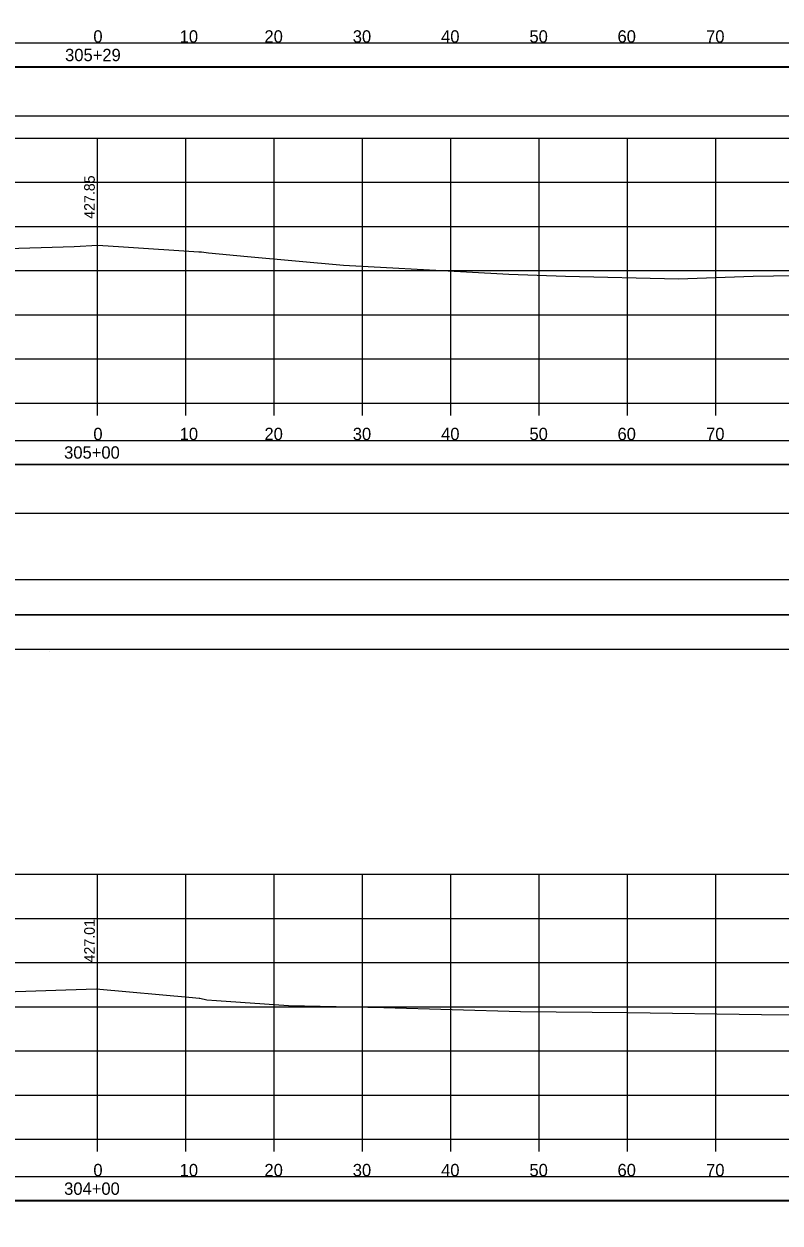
# Model space of a CAD drawing. Extents: x 1371057 to 1372761, y 380005 to 390517.
# Drawn here: x 1372589.5 to 1372675.1, y 389663.8 to 389799.6 of the extents above; entities that cross this region are included whole.
import ezdxf

# ---------------------------------------------------------------- set-up
doc = ezdxf.new("R2010")
doc.units = 0
for name, color, linetype in [('R_Axis', 7, 'Continuous'), ('R_Axis Annot', 7, 'Continuous'), ('R_Border', 7, 'Continuous'), ('R_Dimension', 7, 'Continuous'), ('R_Exist Surface', 7, 'Continuous'), ('R_Grid', 7, 'Continuous'), ('R_No Plot', 7, 'Continuous'), ('R_Xsect Elev', 7, 'Continuous')]:
    doc.layers.add(name, color=color, linetype=linetype)

msp = doc.modelspace()

# ---------------------------------------------------------------- linework, layer by layer
at = {"layer": 'R_Axis'}
for p, q in [((1372447.84, 389756.66), (1372747.84, 389756.66)), ((1372597.84, 389755.26), (1372597.84, 389756.66)), ((1372607.84, 389755.26), (1372607.84, 389756.66)), ((1372617.84, 389755.26), (1372617.84, 389756.66)), ((1372627.84, 389755.26), (1372627.84, 389756.66)), ((1372637.84, 389755.26), (1372637.84, 389756.66)), ((1372647.84, 389755.26), (1372647.84, 389756.66)), ((1372657.84, 389755.26), (1372657.84, 389756.66)), ((1372667.84, 389755.26), (1372667.84, 389756.66)), ((1372447.84, 389673.32), (1372747.84, 389673.32)), ((1372597.84, 389671.92), (1372597.84, 389673.32)), ((1372607.84, 389671.92), (1372607.84, 389673.32)), ((1372617.84, 389671.92), (1372617.84, 389673.32)), ((1372627.84, 389671.92), (1372627.84, 389673.32)), ((1372637.84, 389671.92), (1372637.84, 389673.32)), ((1372647.84, 389671.92), (1372647.84, 389673.32)), ((1372657.84, 389671.92), (1372657.84, 389673.32)), ((1372667.84, 389671.92), (1372667.84, 389673.32))]:
    msp.add_line(p, q, dxfattribs=at)
at = {"layer": 'R_Border'}
for p, q in [((1372756.02, 389736.66), (1372439.84, 389736.66)), ((1372439.84, 389728.78), (1372756.02, 389728.78)), ((1372592.36, 389728.52), (1372592.36, 389728.52)), ((1372592.36, 389728.52), (1372592.36, 389728.52))]:
    msp.add_line(p, q, dxfattribs=at)
at = {"layer": 'R_Dimension'}
for points in [[(1372445.42, 389794.69), (1372750.16, 389794.69), (1372750.16, 389797.39), (1372445.42, 389797.39)], [(1372445.47, 389789.19), (1372750.2, 389789.19), (1372750.2, 389794.71), (1372445.47, 389794.71)], [(1372445.42, 389749.69), (1372750.16, 389749.69), (1372750.16, 389752.39), (1372445.42, 389752.39)], [(1372445.47, 389744.19), (1372750.2, 389744.19), (1372750.2, 389749.71), (1372445.47, 389749.71)], [(1372445.42, 389666.35), (1372750.16, 389666.35), (1372750.16, 389669.05), (1372445.42, 389669.05)], [(1372445.47, 389660.85), (1372750.2, 389660.85), (1372750.2, 389666.37), (1372445.47, 389666.37)]]:
    msp.add_lwpolyline(points, close=True, dxfattribs=at)
at = {"layer": 'R_Exist Surface'}
for points in [[(1372586.4, 389774.1), (1372595.19, 389774.39), (1372597.87, 389774.52), (1372600.79, 389774.33), (1372609.31, 389773.79), (1372609.64, 389773.76), (1372610.4, 389773.68), (1372614.84, 389773.24), (1372625.68, 389772.26), (1372639.64, 389771.5), (1372644.42, 389771.25), (1372650.83, 389771.03), (1372663.61, 389770.72), (1372672.07, 389771.01), (1372683.56, 389771.21), (1372691.95, 389770.91), (1372705.91, 389770.55), (1372715.2, 389770.59), (1372727.99, 389770.76), (1372733.23, 389770.79), (1372738.81, 389770.7), (1372744.62, 389770.6), (1372747.84, 389770.57)], [(1372586.27, 389689.98), (1372597.71, 389690.34), (1372608.59, 389689.35), (1372609.36, 389689.28), (1372609.42, 389689.27), (1372610.24, 389689.11), (1372611.32, 389689.02), (1372619.49, 389688.44), (1372630.28, 389688.21), (1372645.74, 389687.79), (1372657.9, 389687.65), (1372673.02, 389687.45), (1372684.15, 389687.38), (1372695.61, 389687.31), (1372717.55, 389687.46), (1372717.69, 389687.46), (1372735.12, 389687.87), (1372736.13, 389687.89), (1372747.84, 389687.97)]]:
    msp.add_lwpolyline(points, dxfattribs=at)
at = {"layer": 'R_Grid'}
for p, q in [((1372447.84, 389786.66), (1372747.84, 389786.66)), ((1372597.84, 389756.66), (1372597.84, 389786.66)), ((1372607.84, 389756.66), (1372607.84, 389786.66)), ((1372617.84, 389756.66), (1372617.84, 389786.66)), ((1372627.84, 389756.66), (1372627.84, 389786.66)), ((1372637.84, 389756.66), (1372637.84, 389786.66)), ((1372647.84, 389756.66), (1372647.84, 389786.66)), ((1372657.84, 389756.66), (1372657.84, 389786.66)), ((1372667.84, 389756.66), (1372667.84, 389786.66)), ((1372447.84, 389781.66), (1372747.84, 389781.66)), ((1372447.84, 389776.66), (1372747.84, 389776.66)), ((1372447.84, 389771.66), (1372747.84, 389771.66)), ((1372447.84, 389766.66), (1372747.84, 389766.66)), ((1372447.84, 389761.66), (1372747.84, 389761.66)), ((1372447.84, 389756.66), (1372747.84, 389756.66)), ((1372447.84, 389703.32), (1372747.84, 389703.32)), ((1372597.84, 389673.32), (1372597.84, 389703.32)), ((1372607.84, 389673.32), (1372607.84, 389703.32)), ((1372617.84, 389673.32), (1372617.84, 389703.32)), ((1372627.84, 389673.32), (1372627.84, 389703.32)), ((1372637.84, 389673.32), (1372637.84, 389703.32)), ((1372647.84, 389673.32), (1372647.84, 389703.32)), ((1372657.84, 389673.32), (1372657.84, 389703.32)), ((1372667.84, 389673.32), (1372667.84, 389703.32)), ((1372447.84, 389698.32), (1372747.84, 389698.32)), ((1372447.84, 389693.32), (1372747.84, 389693.32)), ((1372447.84, 389688.32), (1372747.84, 389688.32)), ((1372447.84, 389683.32), (1372747.84, 389683.32)), ((1372447.84, 389678.32), (1372747.84, 389678.32)), ((1372447.84, 389673.32), (1372747.84, 389673.32))]:
    msp.add_line(p, q, dxfattribs=at)
at = {"layer": 'R_No Plot'}
msp.add_line((1372427.43, 389732.68), (1372760.77, 389732.68), dxfattribs=at)
msp.add_line((1372427.43, 389732.68), (1372760.77, 389732.68), dxfattribs=at)
for points in [[(1372427.43, 389946.02), (1372760.77, 389946.02), (1372760.77, 389732.68), (1372427.43, 389732.68)], [(1372673.76, 389942.12), (1372693.38, 389942.12), (1372693.38, 389932.24), (1372709.49, 389932.24), (1372732.69, 389932.24), (1372732.81, 389904.09), (1372756.02, 389904.09), (1372756.02, 389736.66), (1372439.84, 389736.66), (1372439.84, 389942.12)], [(1372427.43, 389732.68), (1372760.77, 389732.68), (1372760.77, 389519.34), (1372427.43, 389519.34)], [(1372673.76, 389728.78), (1372693.38, 389728.78), (1372693.38, 389718.9), (1372709.49, 389718.9), (1372732.69, 389718.9), (1372732.81, 389690.75), (1372756.02, 389690.75), (1372756.02, 389523.32), (1372439.84, 389523.32), (1372439.84, 389728.78)]]:
    msp.add_lwpolyline(points, close=True, dxfattribs=at)
at = {"layer": 'R_Xsect Elev'}
for p, q in [((1372597.84, 389774.52), (1372597.84, 389784.52)), ((1372597.84, 389690.33), (1372597.84, 389700.33))]:
    msp.add_line(p, q, dxfattribs=at)

# ---------------------------------------------------------------- texts
at = {"layer": 'R_Axis Annot'}
for s, p in [('0', (1372597.38, 389797.46)), ('10', (1372607.15, 389797.46)), ('20', (1372616.75, 389797.46)), ('30', (1372626.75, 389797.46)), ('40', (1372636.75, 389797.46)), ('50', (1372646.75, 389797.46)), ('60', (1372656.72, 389797.46)), ('70', (1372666.75, 389797.46)), ('305+29', (1372594.18, 389795.36)), ('0', (1372597.38, 389752.46)), ('10', (1372607.15, 389752.46)), ('20', (1372616.75, 389752.46)), ('30', (1372626.75, 389752.46)), ('40', (1372636.75, 389752.46)), ('50', (1372646.75, 389752.46)), ('60', (1372656.72, 389752.46)), ('70', (1372666.75, 389752.46)), ('305+00', (1372594.07, 389750.36)), ('0', (1372597.38, 389669.12)), ('10', (1372607.15, 389669.12)), ('20', (1372616.75, 389669.12)), ('30', (1372626.75, 389669.12)), ('40', (1372636.75, 389669.12)), ('50', (1372646.75, 389669.12)), ('60', (1372656.72, 389669.12)), ('70', (1372666.75, 389669.12)), ('304+00', (1372594.07, 389667.02))]:
    msp.add_text(s, height=1.4, dxfattribs=at).set_placement(p)
at = {"layer": 'R_Xsect Elev'}
for s, p in [('427.85', (1372597.54, 389777.52)), ('427.01', (1372597.54, 389693.33))]:
    msp.add_text(s, height=1.2, rotation=90, dxfattribs=at).set_placement(p)

doc.saveas('drawing.dxf')
